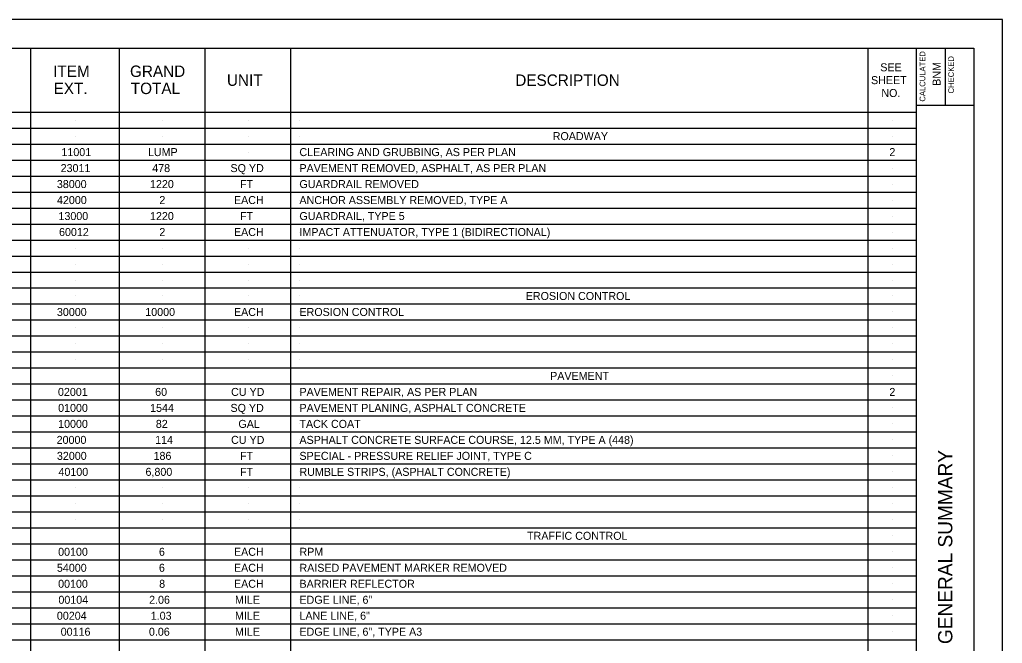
# Model space of a CAD drawing. Extents: x 1 to 35, y -2 to 20.
# Drawn here: x 17.83 to 35.03, y 9.12 to 20.04 of the extents above; entities that cross this region are included whole.
import ezdxf

# ---------------------------------------------------------------- set-up
doc = ezdxf.new("R2010")
doc.units = 0
for name, color, linetype in [('SH_Border', 7, 'Continuous'), ('SH_Cut_Line', 7, 'Continuous'), ('SH_Data', 7, 'Continuous'), ('SH_Text', 7, 'Continuous')]:
    doc.layers.add(name, color=color, linetype=linetype)

msp = doc.modelspace()

# ---------------------------------------------------------------- linework, layer by layer
at = {"layer": 'SH_Border'}
for p, q in [((33.531, -1.457), (33.531, 19.543)), ((34.031, 19.543), (34.031, 18.543)), ((33.531, 18.543), (34.531, 18.543))]:
    msp.add_line(p, q, dxfattribs=at)
msp.add_lwpolyline([(3.031, 19.543), (34.531, 19.543), (34.531, -1.457), (3.031, -1.457)], close=True, dxfattribs=at)
at = {"layer": 'SH_Cut_Line'}
msp.add_lwpolyline([(1.031, -1.957), (35.031, -1.957), (35.031, 20.043), (1.031, 20.043)], close=True, dxfattribs=at)
at = {"layer": 'SH_Data'}
for p, q in [((18.031, -1.457), (18.031, 19.543)), ((19.581, -1.457), (19.581, 19.543)), ((21.081, -1.457), (21.081, 19.543)), ((22.581, -1.457), (22.581, 19.543)), ((32.681, -1.457), (32.681, 19.543)), ((3.031, 18.423), (33.531, 18.423)), ((18.806, 18.283), (18.806, 18.283)), ((20.331, 18.283), (20.331, 18.283)), ((21.831, 18.283), (21.831, 18.283)), ((22.731, 18.283), (22.731, 18.283)), ((33.106, 18.283), (33.106, 18.283)), ((3.031, 18.143), (33.531, 18.143)), ((18.806, 18.003), (18.806, 18.003)), ((20.331, 18.003), (20.331, 18.003)), ((21.831, 18.003), (21.831, 18.003)), ((22.731, 18.003), (22.731, 18.003)), ((33.106, 18.003), (33.106, 18.003)), ((3.031, 17.863), (33.531, 17.863)), ((18.806, 17.723), (18.806, 17.723)), ((20.331, 17.723), (20.331, 17.723)), ((21.831, 17.723), (21.831, 17.723)), ((22.731, 17.723), (22.731, 17.723)), ((33.106, 17.723), (33.106, 17.723)), ((3.031, 17.583), (33.531, 17.583)), ((18.806, 17.443), (18.806, 17.443)), ((20.331, 17.443), (20.331, 17.443)), ((21.831, 17.443), (21.831, 17.443)), ((22.731, 17.443), (22.731, 17.443)), ((33.106, 17.443), (33.106, 17.443)), ((3.031, 17.303), (33.531, 17.303)), ((18.806, 17.163), (18.806, 17.163)), ((20.331, 17.163), (20.331, 17.163)), ((21.831, 17.163), (21.831, 17.163)), ((22.731, 17.163), (22.731, 17.163)), ((33.106, 17.163), (33.106, 17.163)), ((3.031, 17.023), (33.531, 17.023)), ((18.806, 16.883), (18.806, 16.883)), ((20.331, 16.883), (20.331, 16.883)), ((21.831, 16.883), (21.831, 16.883)), ((22.731, 16.883), (22.731, 16.883)), ((33.106, 16.883), (33.106, 16.883)), ((3.031, 16.743), (33.531, 16.743)), ((18.806, 16.603), (18.806, 16.603)), ((20.331, 16.603), (20.331, 16.603)), ((21.831, 16.603), (21.831, 16.603)), ((22.731, 16.603), (22.731, 16.603)), ((33.106, 16.603), (33.106, 16.603)), ((3.031, 16.463), (33.531, 16.463)), ((3.031, 16.183), (33.531, 16.183)), ((18.806, 16.323), (18.806, 16.323)), ((20.331, 16.323), (20.331, 16.323)), ((21.831, 16.323), (21.831, 16.323)), ((22.731, 16.323), (22.731, 16.323)), ((33.106, 16.323), (33.106, 16.323)), ((18.806, 16.043), (18.806, 16.043)), ((20.331, 16.043), (20.331, 16.043)), ((21.831, 16.043), (21.831, 16.043)), ((22.731, 16.043), (22.731, 16.043)), ((33.106, 16.043), (33.106, 16.043)), ((3.031, 15.903), (33.531, 15.903)), ((18.806, 15.763), (18.806, 15.763)), ((20.331, 15.763), (20.331, 15.763)), ((21.831, 15.763), (21.831, 15.763)), ((22.731, 15.763), (22.731, 15.763)), ((33.106, 15.763), (33.106, 15.763)), ((3.031, 15.623), (33.531, 15.623)), ((18.806, 15.483), (18.806, 15.483)), ((20.331, 15.483), (20.331, 15.483)), ((21.831, 15.483), (21.831, 15.483)), ((22.731, 15.483), (22.731, 15.483)), ((33.106, 15.483), (33.106, 15.483)), ((3.031, 15.343), (33.531, 15.343)), ((18.806, 15.203), (18.806, 15.203)), ((20.331, 15.203), (20.331, 15.203)), ((21.831, 15.203), (21.831, 15.203)), ((22.731, 15.203), (22.731, 15.203)), ((33.106, 15.203), (33.106, 15.203)), ((3.031, 15.063), (33.531, 15.063)), ((18.806, 14.923), (18.806, 14.923)), ((20.331, 14.923), (20.331, 14.923)), ((21.831, 14.923), (21.831, 14.923)), ((22.731, 14.923), (22.731, 14.923)), ((33.106, 14.923), (33.106, 14.923)), ((3.031, 14.783), (33.531, 14.783)), ((18.806, 14.643), (18.806, 14.643)), ((20.331, 14.643), (20.331, 14.643)), ((21.831, 14.643), (21.831, 14.643)), ((22.731, 14.643), (22.731, 14.643)), ((33.106, 14.643), (33.106, 14.643)), ((3.031, 14.503), (33.531, 14.503)), ((18.806, 14.363), (18.806, 14.363)), ((20.331, 14.363), (20.331, 14.363)), ((21.831, 14.363), (21.831, 14.363)), ((22.731, 14.363), (22.731, 14.363)), ((33.106, 14.363), (33.106, 14.363)), ((3.031, 14.223), (33.531, 14.223)), ((3.031, 13.943), (33.531, 13.943)), ((18.806, 14.083), (18.806, 14.083)), ((20.331, 14.083), (20.331, 14.083)), ((21.831, 14.083), (21.831, 14.083)), ((22.731, 14.083), (22.731, 14.083)), ((33.106, 14.083), (33.106, 14.083)), ((33.106, 13.803), (33.106, 13.803)), ((3.031, 13.663), (33.531, 13.663)), ((18.806, 13.523), (18.806, 13.523)), ((21.831, 13.523), (21.831, 13.523)), ((22.731, 13.523), (22.731, 13.523)), ((33.106, 13.523), (33.106, 13.523)), ((3.031, 13.383), (33.531, 13.383)), ((18.806, 13.243), (18.806, 13.243)), ((20.331, 13.243), (20.331, 13.243)), ((21.831, 13.243), (21.831, 13.243)), ((22.731, 13.243), (22.731, 13.243)), ((33.106, 13.243), (33.106, 13.243)), ((3.031, 13.103), (33.531, 13.103)), ((18.806, 12.963), (18.806, 12.963)), ((20.331, 12.963), (20.331, 12.963)), ((21.831, 12.963), (21.831, 12.963)), ((22.731, 12.963), (22.731, 12.963)), ((33.106, 12.963), (33.106, 12.963)), ((3.031, 12.823), (33.531, 12.823)), ((18.806, 12.683), (18.806, 12.683)), ((20.331, 12.683), (20.331, 12.683)), ((21.831, 12.683), (21.831, 12.683)), ((22.731, 12.683), (22.731, 12.683)), ((33.106, 12.683), (33.106, 12.683)), ((3.031, 12.543), (33.531, 12.543)), ((18.806, 12.403), (18.806, 12.403)), ((20.331, 12.403), (20.331, 12.403)), ((21.831, 12.403), (21.831, 12.403)), ((22.731, 12.403), (22.731, 12.403)), ((33.106, 12.403), (33.106, 12.403)), ((3.031, 12.263), (33.531, 12.263)), ((18.806, 12.123), (18.806, 12.123)), ((18.806, 12.123), (18.806, 12.123)), ((20.331, 12.123), (20.331, 12.123)), ((20.331, 12.123), (20.331, 12.123)), ((21.831, 12.123), (21.831, 12.123)), ((21.831, 12.123), (21.831, 12.123)), ((22.731, 12.123), (22.731, 12.123)), ((22.731, 12.123), (22.731, 12.123)), ((33.106, 12.123), (33.106, 12.123)), ((3.031, 11.983), (33.531, 11.983)), ((3.031, 11.703), (33.531, 11.703)), ((18.806, 11.843), (18.806, 11.843)), ((20.331, 11.843), (20.331, 11.843)), ((21.831, 11.843), (21.831, 11.843)), ((22.731, 11.843), (22.731, 11.843)), ((33.106, 11.843), (33.106, 11.843)), ((18.806, 11.563), (18.806, 11.563)), ((20.331, 11.563), (20.331, 11.563)), ((21.831, 11.563), (21.831, 11.563)), ((22.731, 11.563), (22.731, 11.563)), ((33.106, 11.563), (33.106, 11.563)), ((3.031, 11.423), (33.531, 11.423)), ((18.806, 11.283), (18.806, 11.283)), ((20.331, 11.283), (20.331, 11.283)), ((21.831, 11.283), (21.831, 11.283)), ((22.731, 11.283), (22.731, 11.283)), ((33.106, 11.283), (33.106, 11.283)), ((3.031, 11.143), (33.531, 11.143)), ((3.031, 10.863), (33.531, 10.863)), ((33.106, 11.003), (33.106, 11.003)), ((18.806, 10.723), (18.806, 10.723)), ((20.331, 10.723), (20.331, 10.723)), ((21.831, 10.723), (21.831, 10.723)), ((22.731, 10.723), (22.731, 10.723)), ((33.106, 10.723), (33.106, 10.723)), ((3.031, 10.583), (33.531, 10.583)), ((18.806, 10.443), (18.806, 10.443)), ((20.331, 10.443), (20.331, 10.443)), ((21.831, 10.443), (21.831, 10.443)), ((22.731, 10.443), (22.731, 10.443)), ((33.106, 10.443), (33.106, 10.443)), ((3.031, 10.303), (33.531, 10.303)), ((18.806, 10.163), (18.806, 10.163)), ((20.331, 10.163), (20.331, 10.163)), ((21.831, 10.163), (21.831, 10.163)), ((22.731, 10.163), (22.731, 10.163)), ((33.106, 10.163), (33.106, 10.163)), ((3.031, 10.023), (33.531, 10.023)), ((18.806, 9.883), (18.806, 9.883)), ((20.331, 9.883), (20.331, 9.883)), ((21.831, 9.883), (21.831, 9.883)), ((22.731, 9.883), (22.731, 9.883)), ((33.106, 9.883), (33.106, 9.883)), ((3.031, 9.743), (33.531, 9.743)), ((3.031, 9.463), (33.531, 9.463)), ((18.806, 9.603), (18.806, 9.603)), ((20.331, 9.603), (20.331, 9.603)), ((21.831, 9.603), (21.831, 9.603)), ((22.731, 9.603), (22.731, 9.603)), ((33.106, 9.603), (33.106, 9.603)), ((18.806, 9.323), (18.806, 9.323)), ((20.331, 9.323), (20.331, 9.323)), ((21.831, 9.323), (21.831, 9.323)), ((22.731, 9.323), (22.731, 9.323)), ((33.106, 9.323), (33.106, 9.323)), ((3.031, 9.183), (33.531, 9.183))]:
    msp.add_line(p, q, dxfattribs=at)

# ---------------------------------------------------------------- texts
for s, height, p in [('CALCULATED', 0.1, (33.683, 18.607)), ('BNM', 0.14, (33.951, 18.884)), ('CHECKED', 0.1, (34.183, 18.751)), ('GENERAL SUMMARY', 0.25, (34.156, 9.107))]:
    msp.add_text(s, height=height, rotation=90, dxfattribs=at).set_placement(p)
for s, height, p in [('SEE', 0.14, (32.895, 19.138)), ('ITEM', 0.2, (18.422, 19.039)), ('GRAND', 0.2, (19.766, 19.039)), ('EXT.', 0.2, (18.429, 18.739)), ('TOTAL', 0.2, (19.78, 18.739)), ('UNIT', 0.2, (21.462, 18.883)), ('DESCRIPTION', 0.2, (26.508, 18.883)), ('SHEET', 0.14, (32.733, 18.913)), ('NO.', 0.14, (32.914, 18.688))]:
    msp.add_text(s, height=height, dxfattribs=at).set_placement(p)
at = {"layer": 'SH_Text'}
for s, p in [('ROADWAY', (27.163, 17.933)), ('11001', (18.566, 17.653)), ('LUMP', (20.08, 17.653)), ('CLEARING AND GRUBBING, AS PER PLAN', (22.731, 17.653)), ('2', (33.054, 17.653)), ('23011', (18.552, 17.373)), ('478', (20.155, 17.373)), ('SQ YD', (21.524, 17.373)), ('PAVEMENT REMOVED, ASPHALT, AS PER PLAN', (22.731, 17.373)), ('38000', (18.486, 17.093)), ('1220', (20.116, 17.093)), ('FT', (21.69, 17.093)), ('GUARDRAIL REMOVED', (22.731, 17.093)), ('42000', (18.488, 16.813)), ('2', (20.279, 16.813)), ('EACH', (21.585, 16.813)), ('ANCHOR ASSEMBLY REMOVED, TYPE A', (22.731, 16.813)), ('13000', (18.514, 16.533)), ('1220', (20.116, 16.533)), ('FT', (21.69, 16.533)), ('GUARDRAIL, TYPE 5', (22.731, 16.533)), ('60012', (18.524, 16.253)), ('2', (20.279, 16.253)), ('EACH', (21.585, 16.253)), ('IMPACT ATTENUATOR, TYPE 1 (BIDIRECTIONAL)', (22.731, 16.253)), ('EROSION CONTROL', (26.691, 15.133)), ('30000', (18.487, 14.853)), ('10000', (20.033, 14.853)), ('EACH', (21.585, 14.853)), ('EROSION CONTROL', (22.731, 14.853)), ('PAVEMENT', (27.118, 13.733)), ('02001', (18.505, 13.453)), ('60', (20.206, 13.453)), ('CU YD', (21.535, 13.453)), ('PAVEMENT REPAIR, AS PER PLAN', (22.731, 13.453)), ('2', (33.054, 13.453)), ('01000', (18.508, 13.173)), ('1544', (20.118, 13.173)), ('SQ YD', (21.524, 13.173)), ('PAVEMENT PLANING, ASPHALT CONCRETE', (22.731, 13.173)), ('10000', (18.508, 12.893)), ('82', (20.218, 12.893)), ('GAL', (21.663, 12.893)), ('TACK COAT', (22.731, 12.893)), ('20000', (18.482, 12.613)), ('114', (20.206, 12.613)), ('CU YD', (21.535, 12.613)), ('ASPHALT CONCRETE SURFACE COURSE, 12.5 MM, TYPE A (448)', (22.731, 12.613)), ('32000', (18.487, 12.333)), ('186', (20.178, 12.333)), ('FT', (21.69, 12.333)), ('SPECIAL - PRESSURE RELIEF JOINT, TYPE C', (22.731, 12.333)), ('40100', (18.514, 12.053)), ('6,800', (20.037, 12.053)), ('FT', (21.69, 12.053)), ('RUMBLE STRIPS, (ASPHALT CONCRETE)', (22.731, 12.053)), ('TRAFFIC CONTROL', (26.714, 10.933)), ('00100', (18.508, 10.653)), ('6', (20.272, 10.653)), ('EACH', (21.585, 10.653)), ('RPM', (22.731, 10.653)), ('54000', (18.487, 10.373)), ('6', (20.272, 10.373)), ('EACH', (21.585, 10.373)), ('RAISED PAVEMENT MARKER REMOVED', (22.731, 10.373)), ('00100', (18.508, 10.093)), ('8', (20.276, 10.093)), ('EACH', (21.585, 10.093)), ('BARRIER REFLECTOR', (22.731, 10.093)), ('00104', (18.513, 9.813)), ('2.06', (20.1, 9.813)), ('MILE', (21.603, 9.813)), ('EDGE LINE, 6"', (22.731, 9.813)), ('00204', (18.486, 9.533)), ('1.03', (20.129, 9.533)), ('MILE', (21.603, 9.533)), ('LANE LINE, 6"', (22.731, 9.533)), ('00116', (18.553, 9.253)), ('0.06', (20.097, 9.253)), ('MILE', (21.603, 9.253)), ('EDGE LINE, 6", TYPE A3', (22.731, 9.253))]:
    msp.add_text(s, height=0.14, dxfattribs=at).set_placement(p)

doc.saveas('drawing.dxf')
